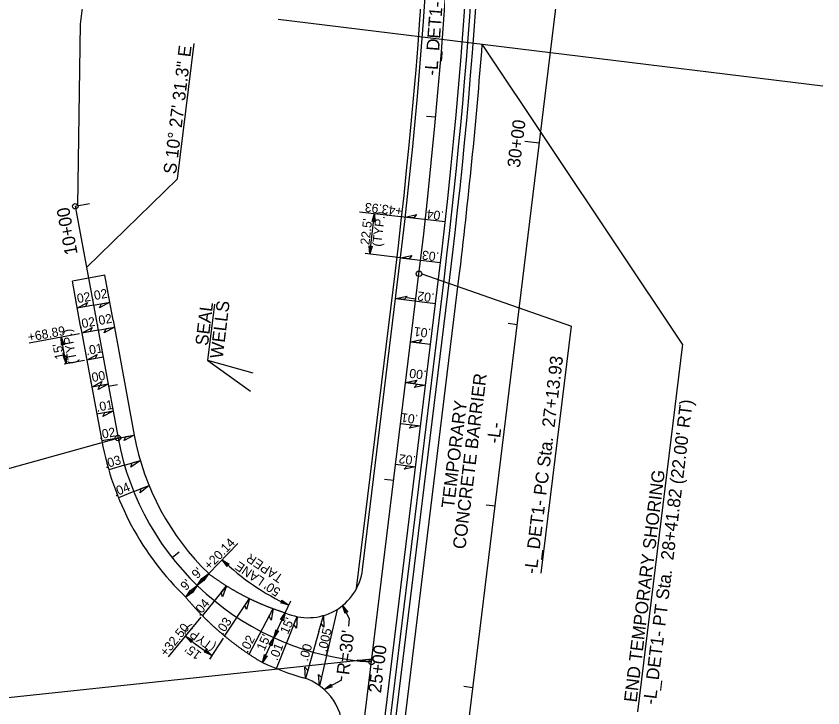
# Model space of a CAD drawing. Extents: x 473658 to 481584, y 489119 to 506230.
# Drawn here: x 481102.1 to 481543.2, y 490771.8 to 491150.2 of the extents above; entities that cross this region are included whole.
import ezdxf

# ---------------------------------------------------------------- set-up
doc = ezdxf.new("R2010")
doc.units = 0
for name, color, linetype in [('Exist Structure Minor Pipes CMP 60 Inch', 7, 'Continuous'), ('Prop Conc Barrier', 7, 'Continuous'), ('Prop Dimension', 7, 'Continuous'), ('Prop EOT', 7, 'Continuous'), ('Prop Horizontal Alignment', 7, 'Continuous'), ('Prop Horizontal Alignment Direction Label', 7, 'Continuous'), ('Prop Horizontal Alignment Station Label', 7, 'Continuous'), ('Prop Horizontal Alignment Tick Label', 7, 'Continuous'), ('Prop Horizontal Alignment Tick Large', 7, 'Continuous'), ('Prop Horizontal Alignment Tick Small', 7, 'Continuous'), ('Prop Paved Shoulder', 7, 'Continuous'), ('Prop Superelevation  Arrow CELL', 7, 'Continuous'), ('Prop Superelevation Label', 7, 'Continuous'), ('Scratch_Level_5', 7, 'Continuous'), ('Sheet Plan And Profile CELL', 7, 'Continuous'), ('Sheet Profile Grid Major CELL', 7, 'Continuous')]:
    doc.layers.add(name, color=color, linetype=linetype)

msp = doc.modelspace()

# ---------------------------------------------------------------- linework, layer by layer
at = {"layer": 'Exist Structure Minor Pipes CMP 60 Inch'}
msp.add_line((481254.45, 490271.98), (481344.18, 491006.64), dxfattribs=at)
msp.add_arc((478448.7, 491360.28), 2917, 353.03651, 355.56761, dxfattribs=at)
at = {"layer": 'Prop Conc Barrier'}
msp.add_line((481218.72, 490045.39), (481336.24, 491007.62), dxfattribs=at)
msp.add_arc((478448.2, 491360.34), 2909.5, 353.03651, 8.05328, dxfattribs=at)
at = {"layer": 'Prop Dimension'}
for p, q in [((481207.37, 490845.26), (481223.26, 490861.72)), ((481194.86, 490832.32), (481207.37, 490845.26)), ((481249.27, 490823.87), (481252.27, 490830.45)), ((481284.43, 490820.58), (481280.54, 490827.79)), ((481236.81, 490796.58), (481249.27, 490823.87)), ((481283.94, 490816.6), (481284.43, 490820.58)), ((481279.91, 490787.04), (481270.57, 490781.87)), ((481279.91, 490787.04), (481280.15, 490788.94))]:
    msp.add_line(p, q, dxfattribs=at)
for points in [[(481217.48, 490849.24), (481214.72, 490852.88), (481218.58, 490850.37), (481217.61, 490850.18)], [(481203.69, 490842.57), (481207.37, 490845.26), (481204.8, 490841.45), (481204.63, 490842.42)], [(481204.8, 490841.49), (481201.12, 490838.79), (481203.69, 490842.6), (481203.86, 490841.63)], [(481198.55, 490835.02), (481194.86, 490832.32), (481197.43, 490836.13), (481197.61, 490835.16)], [(481197.43, 490836.09), (481201.12, 490838.79), (481198.55, 490834.98), (481198.37, 490835.95)], [(481247.44, 490830.68), (481251.17, 490828.04), (481246.74, 490829.27), (481247.61, 490829.74)], [(481281.99, 490823.46), (481280.54, 490827.79), (481283.39, 490824.19), (481282.41, 490824.32)], [(481246.7, 490820.1), (481249.27, 490823.87), (481248.12, 490819.42), (481247.63, 490820.28)], [(481245.61, 490814), (481243.04, 490810.23), (481244.19, 490814.67), (481244.68, 490813.82)], [(481240.47, 490806.45), (481243.04, 490810.23), (481241.89, 490805.78), (481241.4, 490806.63)], [(481239.39, 490800.35), (481236.81, 490796.58), (481237.96, 490801.03), (481238.45, 490800.17)], [(481274.88, 490783.37), (481270.57, 490781.87), (481274.14, 490784.76), (481274.03, 490783.78)]]:
    msp.add_lwpolyline(points, close=True, dxfattribs=at)
msp.add_arc((481305.32, 490946.68), 130.41, 225.9952, 245.4664, dxfattribs=at)
at = {"layer": 'Prop EOT'}
for p, q in [((481150.6, 491008.51), (481132.88, 491005.24)), ((481155.07, 490983.91), (481150.6, 491008.51)), ((481195.32, 489878.54), (481333.26, 491007.97)), ((481291.5, 490847.53), (481311.43, 491010.64)), ((481137.37, 490980.65), (481132.88, 491005.24)), ((481137.37, 490980.65), (481148.97, 490917.82)), ((481155.07, 490983.91), (481166.67, 490921.09))]:
    msp.add_line(p, q, dxfattribs=at)
for centre, radius, start, end in [((478448.7, 491360.28), 2906, 353.03651, 11.67572), ((478448.7, 491360.28), 2884, 353.03651, 10.48724), ((481305.32, 490946.68), 141, 190.4587, 225.9952), ((481305.32, 490946.68), 159, 190.4587, 225.9952), ((481261.73, 490851.16), 30, 245.4663, 353.0365), ((481305.32, 490946.68), 165, 245.4664, 253.6818), ((481250.54, 490759.54), 30, 353.0365, 73.6818)]:
    msp.add_arc(centre, radius, start, end, dxfattribs=at)
for points in [[(481207.37, 490845.26), (481207.89, 490844.87), (481208.42, 490844.49), (481208.94, 490844.1), (481209.47, 490843.72), (481210, 490843.34), (481210.53, 490842.96), (481211.06, 490842.59), (481211.59, 490842.22), (481212.13, 490841.85), (481212.66, 490841.48), (481213.2, 490841.12), (481213.74, 490840.76), (481214.28, 490840.4), (481214.82, 490840.05), (481215.37, 490839.69), (481215.91, 490839.34), (481216.45, 490839), (481217, 490838.65), (481217.55, 490838.31), (481218.1, 490837.97), (481218.65, 490837.64), (481219.2, 490837.3), (481219.75, 490836.97), (481220.31, 490836.65), (481220.86, 490836.32), (481221.42, 490836), (481221.98, 490835.68), (481222.54, 490835.36), (481223.1, 490835.05), (481223.66, 490834.74), (481224.22, 490834.43), (481224.79, 490834.12), (481225.35, 490833.82), (481225.92, 490833.52), (481226.48, 490833.23), (481227.05, 490832.93), (481227.62, 490832.64), (481228.19, 490832.35), (481228.76, 490832.07), (481229.33, 490831.78), (481229.91, 490831.5), (481230.48, 490831.23), (481231.05, 490830.95), (481231.63, 490830.68), (481232.21, 490830.41), (481232.78, 490830.15), (481233.36, 490829.88), (481233.94, 490829.62), (481234.52, 490829.37), (481235.1, 490829.11), (481235.68, 490828.86), (481236.27, 490828.61), (481236.85, 490828.37), (481237.44, 490828.12), (481238.02, 490827.88), (481238.61, 490827.65), (481239.19, 490827.41), (481239.78, 490827.18), (481240.37, 490826.95), (481240.96, 490826.73), (481241.55, 490826.5), (481242.14, 490826.28), (481242.73, 490826.07), (481243.32, 490825.85), (481243.91, 490825.64), (481244.51, 490825.43), (481245.1, 490825.23), (481245.69, 490825.03), (481246.29, 490824.83), (481246.88, 490824.63), (481247.48, 490824.44), (481248.07, 490824.24), (481249.27, 490823.87)], [(481194.86, 490832.32), (481195.33, 490831.75), (481195.81, 490831.19), (481196.28, 490830.63), (481196.76, 490830.07), (481197.24, 490829.51), (481197.73, 490828.96), (481198.22, 490828.41), (481198.71, 490827.85), (481199.2, 490827.31), (481199.7, 490826.76), (481200.19, 490826.21), (481200.7, 490825.67), (481201.2, 490825.13), (481201.71, 490824.59), (481202.22, 490824.05), (481202.73, 490823.52), (481203.24, 490822.99), (481203.76, 490822.46), (481204.28, 490821.93), (481204.8, 490821.4), (481205.33, 490820.88), (481205.86, 490820.36), (481206.39, 490819.84), (481206.92, 490819.32), (481207.46, 490818.81), (481208, 490818.29), (481208.54, 490817.78), (481209.09, 490817.28), (481209.63, 490816.77), (481210.18, 490816.27), (481210.74, 490815.76), (481211.29, 490815.27), (481211.85, 490814.77), (481212.41, 490814.27), (481212.97, 490813.78), (481213.54, 490813.29), (481214.11, 490812.81), (481214.68, 490812.32), (481215.25, 490811.84), (481215.82, 490811.36), (481216.4, 490810.88), (481216.98, 490810.41), (481217.57, 490809.93), (481218.15, 490809.46), (481218.74, 490809), (481219.33, 490808.53), (481219.92, 490808.07), (481220.52, 490807.61), (481221.12, 490807.15), (481221.72, 490806.7), (481222.32, 490806.24), (481222.92, 490805.8), (481223.53, 490805.35), (481224.14, 490804.9), (481224.75, 490804.46), (481225.37, 490804.02), (481225.98, 490803.59), (481226.6, 490803.15), (481227.22, 490802.72), (481227.85, 490802.29), (481228.47, 490801.87), (481229.1, 490801.44), (481229.73, 490801.02), (481230.36, 490800.6), (481231, 490800.19), (481231.64, 490799.78), (481232.28, 490799.37), (481232.92, 490798.96), (481233.56, 490798.56), (481234.21, 490798.16), (481234.85, 490797.76), (481235.51, 490797.36), (481236.81, 490796.58)]]:
    msp.add_spline(points, degree=3, dxfattribs=at)
at = {"layer": 'Prop Horizontal Alignment'}
for p, q in [((481200.24, 489541.46), (481402.27, 491195.58)), ((481134.42, 491046.2), (481157.82, 490919.45)), ((481134.42, 491046.2), (481157.82, 490919.45)), ((481184.4, 489879.88), (481322.35, 491009.3))]:
    msp.add_line(p, q, dxfattribs=at)
for centre, radius, start, end in [((478448.7, 491360.28), 2895, 353.03651, 18.70399), ((481305.32, 490946.68), 150, 190.4587, 266.5925), ((481305.32, 490946.68), 150, 190.4587, 266.5925)]:
    msp.add_arc(centre, radius, start, end, dxfattribs=at)
at = {"layer": 'Prop Horizontal Alignment Station Label'}
for p, q in [((481137.28, 491145.89), (481155.02, 491291.11)), ((481135.9, 491046.47), (481137.28, 491145.94)), ((481190.4, 491061.13), (481199.46, 491135.33)), ((481466.38, 490970.79), (481356.98, 491134.85)), ((481140.61, 491012.67), (481190.4, 491061.13)), ((481323.85, 491009.3), (481405.67, 490980.62)), ((481389.17, 490845.55), (481405.67, 490980.62)), ((481466.38, 490970.79), (481441.81, 490769.61)), ((481159.29, 490919.73), (481016.13, 490879.8)), ((481296.5, 490798.45), (481094.33, 490776.95))]:
    msp.add_line(p, q, dxfattribs=at)
for centre in [(481134.42, 491046.2), (481322.35, 491009.3), (481157.82, 490919.45), (481296.41, 490796.95)]:
    msp.add_circle(centre, 1.5, dxfattribs=at)
at = {"layer": 'Prop Horizontal Alignment Tick Large'}
for p, q in [((481388.23, 491080.67), (481380.29, 491081.64)), ((481134.42, 491046.2), (481142.29, 491047.65)), ((481296.41, 490796.95), (481288.47, 490797.92))]:
    msp.add_line(p, q, dxfattribs=at)
at = {"layer": 'Prop Horizontal Alignment Tick Small'}
for p, q in [((481331.51, 491094.88), (481326.53, 491095.34)), ((481320.66, 490995.47), (481315.69, 490996.08)), ((481376.11, 490981.4), (481371.14, 490982.01)), ((481152.57, 490947.86), (481157.49, 490948.77)), ((481308.53, 490896.21), (481303.57, 490896.82)), ((481363.98, 490882.14), (481359.02, 490882.75)), ((481187.37, 490854.02), (481191.3, 490857.11)), ((481271.82, 490800.47), (481272.94, 490805.35)), ((481351.86, 490782.88), (481346.9, 490783.48))]:
    msp.add_line(p, q, dxfattribs=at)
at = {"layer": 'Prop Paved Shoulder'}
for p, q in [((481221.7, 490045.03), (481339.22, 491007.26)), ((481288.21, 490837.08), (481309.44, 491010.88))]:
    msp.add_line(p, q, dxfattribs=at)
for centre, radius, start, end in [((478448.7, 491360.28), 2882, 353.03651, 10.60669), ((478448.2, 491360.26), 2912.5, 353.03855, 8.56944)]:
    msp.add_arc(centre, radius, start, end, dxfattribs=at)
at = {"layer": 'Prop Superelevation  Arrow CELL'}
for p, q in [((481295.45, 491020.07), (481297.97, 491042.21)), ((481129.53, 490959.99), (481126.8, 490974.72))]:
    msp.add_line(p, q, dxfattribs=at)
for points in [[(481296.69, 491037.83), (481297.97, 491042.21), (481298.25, 491037.62), (481297.52, 491038.28)], [(481314.9, 491040.32), (481321.08, 491041.64), (481319.49, 491039.81)], [(481296.73, 491024.45), (481295.45, 491020.07), (481295.17, 491024.65), (481295.9, 491023.99)], [(481312.32, 491018.05), (481318.52, 491019.33), (481316.91, 491017.5)], [(481135.52, 490990.47), (481141.06, 490993.53), (481140.07, 490991.31)], [(481153.28, 490993.75), (481147.75, 490990.7), (481148.74, 490992.91)], [(481309.61, 490995.74), (481315.81, 490997), (481314.2, 490995.18)], [(481138.05, 490976.82), (481143.58, 490979.87), (481142.59, 490977.66)], [(481155.8, 490980.1), (481150.27, 490977.04), (481151.26, 490979.26)], [(481126.86, 490970.16), (481126.8, 490974.72), (481128.41, 490970.42), (481127.52, 490970.84)], [(481317.8, 490972.08), (481324, 490973.33), (481322.39, 490971.52)], [(481129.46, 490964.56), (481129.53, 490959.99), (481127.9, 490964.29), (481128.8, 490963.87)], [(481140.77, 490962.07), (481146.31, 490965.12), (481145.32, 490962.91)], [(481143.49, 490947.32), (481149.03, 490950.37), (481148.04, 490948.16)], [(481315.07, 490949.74), (481321.27, 490951), (481319.66, 490949.18)], [(481152.4, 490948.97), (481146.86, 490945.91), (481147.85, 490948.13)], [(481325.99, 490948.41), (481319.79, 490947.15), (481321.4, 490948.97)], [(481155.12, 490934.22), (481149.58, 490931.16), (481150.57, 490933.38)], [(481323.26, 490926.08), (481317.06, 490924.82), (481318.67, 490926.64)], [(481166.7, 490921.09), (481161.16, 490918.04), (481162.15, 490920.25)], [(481170.02, 490907.12), (481164.82, 490903.51), (481165.58, 490905.82)], [(481320.53, 490903.74), (481314.34, 490902.48), (481315.94, 490904.3)], [(481174.75, 490893.55), (481169.95, 490889.44), (481170.47, 490891.81)], [(481217.16, 490838.55), (481214.92, 490832.64), (481214.24, 490834.97)], [(481229.63, 490831.67), (481228, 490825.56), (481227.09, 490827.81)], [(481242.55, 490826.13), (481241.55, 490819.89), (481240.41, 490822.03)], [(481255.7, 490821.77), (481255.34, 490815.46), (481253.99, 490817.48)], [(481270.07, 490822.37), (481270.37, 490816.06), (481268.82, 490817.92)], [(481197.73, 490807.6), (481194.74, 490811.05), (481198.75, 490808.8), (481197.79, 490808.55)], [(481205.76, 490803.7), (481209.05, 490800.54), (481204.86, 490802.41), (481205.78, 490802.75)], [(481260.32, 490787.86), (481260.02, 490794.18), (481261.57, 490792.31)], [(481268.02, 490783.88), (481267.41, 490790.17), (481269.05, 490788.39)]]:
    msp.add_lwpolyline(points, close=True, dxfattribs=at)
msp.add_arc((481305.32, 490946.68), 175, 230.8081, 236.6263, dxfattribs=at)
at = {"layer": 'Prop Superelevation Label'}
for p, q in [((481289.76, 491043.13), (481336.76, 491037.88)), ((481312.31, 491018.05), (481292.92, 491020.37)), ((481312.31, 491018.05), (481334.17, 491015.44)), ((481144.4, 490992.11), (481153.28, 490993.75)), ((481309.61, 490995.74), (481331.45, 490993.08)), ((481144.4, 490992.11), (481135.52, 490990.47)), ((481109.25, 490971.48), (481136.76, 490976.56)), ((481146.93, 490978.46), (481138.05, 490976.82)), ((481146.93, 490978.46), (481155.8, 490980.1)), ((481317.8, 490972.08), (481328.72, 490970.74)), ((481149.65, 490963.71), (481140.77, 490962.07)), ((481139.48, 490961.83), (481128.37, 490959.78)), ((481315.07, 490949.74), (481325.99, 490948.41)), ((481152.37, 490948.96), (481143.49, 490947.32)), ((481155.09, 490934.2), (481146.21, 490932.57)), ((481312.34, 490927.41), (481323.26, 490926.08)), ((481157.82, 490919.45), (481148.94, 490917.82)), ((481157.82, 490919.45), (481166.7, 490921.09)), ((481161.35, 490904.58), (481170.02, 490907.12)), ((481161.35, 490904.58), (481152.69, 490902.05)), ((481309.62, 490905.07), (481320.53, 490903.74)), ((481166.39, 490890.15), (481174.75, 490893.55)), ((481166.39, 490890.15), (481158.02, 490886.75)), ((481217.16, 490838.55), (481203.91, 490822.3)), ((481216.11, 490811.12), (481229.63, 490831.67)), ((481229.54, 490801.15), (481242.55, 490826.13)), ((481185.47, 490799.69), (481203.23, 490821.47)), ((481244.4, 490793.34), (481255.7, 490821.77)), ((481267.62, 490813.68), (481270.07, 490822.37)), ((481277.61, 490825.72), (481268.02, 490783.91)), ((481267.62, 490813.68), (481260.31, 490787.9)), ((481215.38, 490810.01), (481207.74, 490798.41))]:
    msp.add_line(p, q, dxfattribs=at)
at = {"layer": 'Scratch_Level_5'}
msp.add_line((481201.27, 489877.82), (481339.22, 491007.24), dxfattribs=at)
at = {"layer": 'Sheet Plan And Profile CELL'}
msp.add_line((481245.4, 491148.48), (481543.19, 491112.11), dxfattribs=at)
at = {"layer": 'Sheet Profile Grid Major CELL'}
for p, q in [((481206.95, 490961.81), (481210.71, 490992.64)), ((481231.64, 490954.99), (481206.95, 490961.81)), ((481206.95, 490961.81), (481230.18, 490945.16))]:
    msp.add_line(p, q, dxfattribs=at)

# ---------------------------------------------------------------- texts
at = {"layer": 'Prop Horizontal Alignment Direction Label'}
for s, rotation, p in [('-L_DET1-', 85.6162, (481332.31, 491117.49)), ('S 10%%d 27\' 31.3" E', 83.0365, (481189.5, 491063.5)), ('-L-', 83.0365, (481366.31, 490916.18))]:
    msp.add_text(s, height=7, rotation=rotation, dxfattribs=at).set_placement(p)
at = {"layer": 'Prop Horizontal Alignment Station Label'}
for s, p in [('-L_DET1- PC Sta.  27+13.93', (481386.69, 490844.89)), ("-L_DET1- PT Sta.  28+41.82 (22.00' RT)", (481451.76, 490773.33)), ('END TEMPORARY SHORING', (481441.34, 490774.61))]:
    msp.add_text(s, height=7, rotation=83.0365, dxfattribs=at).set_placement(p)
at = {"layer": 'Prop Horizontal Alignment Tick Label'}
for s, rotation, p in [('30+00', 83.0365, (481377.5, 491067.04)), ('10+00', 100.4587, (481135.77, 491020.21)), ('25+00', 83.0365, (481301.56, 490779.69))]:
    msp.add_text(s, height=7, rotation=rotation, dxfattribs=at).set_placement(p)
at = {"layer": 'Prop Superelevation  Arrow CELL'}
for s, rotation, p in [('+43.93', 173.501, (481313.61, 491045.88)), ('(TYP.)', 83.501, (481301.7, 491023.94)), ("22.5'", 83.501, (481295.21, 491024.88)), ('+68.89', 10.4685, (481108.96, 490972.13)), ('(TYP.)', 100.5207, (481135.59, 490960.4)), ("15'", 100.5207, (481128.49, 490962.91)), ('+32.50', 50.8081, (481184.06, 490799.55)), ('(TYP.)', 143.7172, (481211.63, 490806.04)), ("15'", 143.7172, (481203.83, 490801.78))]:
    msp.add_text(s, height=5, rotation=rotation, dxfattribs=at).set_placement(p)
at = {"layer": 'Prop Superelevation Label'}
for s, rotation, p in [('.04', 173.0365, (481336.18, 491043.32)), ('.03', 173.0365, (481333.57, 491020.91)), ('.02', 10.4587, (481134, 490992.85)), ('.02', 10.4587, (481143.26, 490994.56)), ('.02', 173.0365, (481331.03, 490998.53)), ('.02', 10.4587, (481136.52, 490979.19)), ('.02', 10.4587, (481145.78, 490980.9)), ('.01', 173.0365, (481329.14, 490979.1)), ('.01', 10.4587, (481140.65, 490964.7)), ('.00', 10.4587, (481142.05, 490949.71)), ('.00', 173.0365, (481326.65, 490956.28)), ('.01', 10.4587, (481146.29, 490933.75)), ('.01', 173.0365, (481322.13, 490932.01)), ('.02', 10.4587, (481147.61, 490918.74)), ('.03', 16.3, (481150.96, 490902.74)), ('.02', 173.0365, (481320.9, 490909.49)), ('.04', 22.1414, (481156.29, 490887.28)), ('.04', 50.8081, (481202.41, 490821.68)), ('.03', 56.6501, (481215.09, 490811.43)), ('.005', 77.1439, (481271.83, 490802.11)), ('.02', 62.4915, (481228.64, 490801.64)), ('.01', 68.3329, (481244.89, 490797.33)), ('.00', 74.2482, (481261.54, 490797.1))]:
    msp.add_text(s, height=5, rotation=rotation, dxfattribs=at).set_placement(p)
at = {"layer": 'Sheet Profile Grid Major CELL'}
for s, height, rotation, p in [('WELLS', 7, 83.0365, (481215.04, 490962.62)), ('SEAL ', 7, 83.0365, (481206.96, 490969.66)), ('CONCRETE BARRIER', 7, 83.0365, (481347.71, 490858.36)), ('TEMPORARY', 7, 83.0365, (481341.49, 490880.69)), ('+20.14', 5, 45.9952, (481207.87, 490846.92)), ('TAPER', 5, 145.7308, (481248.52, 490843.98)), ("9'", 5, 45.9952, (481201.09, 490842.1)), ("50' LANE ", 5, 145.7308, (481247.13, 490836.46)), ("9'", 5, 45.9952, (481194.93, 490835.63)), ("15'", 5, 65.4664, (481250.67, 490811.75)), ("R=30'", 7, 83.0365, (481284.17, 490789.58)), ("15'", 5, 65.4664, (481237.79, 490802.61))]:
    msp.add_text(s, height=height, rotation=rotation, dxfattribs=at).set_placement(p)

doc.saveas('drawing.dxf')
